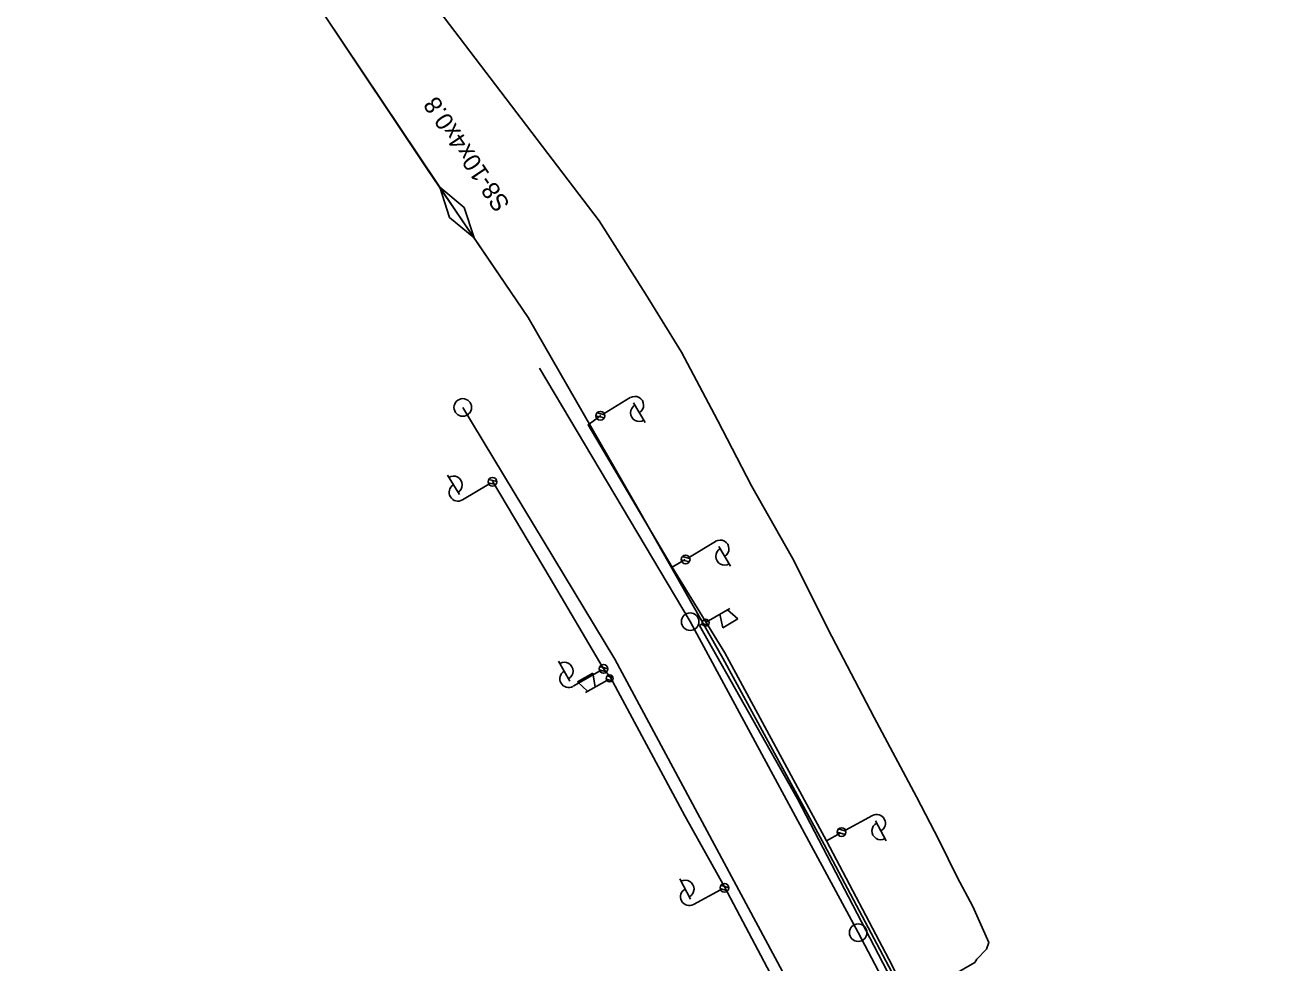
# Model space of a CAD drawing. Extents: x -748507 to -687366, y -1057342 to -1024924.
# Drawn here: x -745968.5 to -745824.4, y -1027172.3 to -1027065.4 of the extents above; entities that cross this region are included whole.
import ezdxf

# ---------------------------------------------------------------- set-up
doc = ezdxf.new("R2010")
doc.units = 0
for name, color, linetype in [('DK + TKK - SŽDC', 7, 'Continuous'), ('kanalizace ČD', 7, 'Continuous'), ('Sděl MK - SŽDC', 7, 'Continuous'), ('TK+DOK_Pha Holešovice - Kralupy', 7, 'Continuous'), ('Vedení NN - SŽDC', 7, 'Continuous'), ('ČEZ Distribuce - NN', 7, 'Continuous')]:
    doc.layers.add(name, color=color, linetype=linetype)

msp = doc.modelspace()

# ---------------------------------------------------------------- linework, layer by layer
at = {"layer": 'DK + TKK - SŽDC'}
msp.add_lwpolyline([(-745853.98, -1027207.17), (-745858.09, -1027198.24), (-745865.58, -1027181.9), (-745866.6, -1027178.75), (-745867.49, -1027177.72), (-745877.49, -1027158.8), (-745889.04, -1027137.58), (-745898.56, -1027120.82), (-745911.21, -1027098.73), (-745922.68, -1027081.89), (-745934.42, -1027064.27), (-745946.08, -1027047.16), (-745963.34, -1027024.99), (-745977.95, -1027005.62), (-745988.16, -1026993.76), (-745996.58, -1026983.71), (-746011.66, -1026965.97), (-746032.06, -1026944.1), (-746050.01, -1026925.99), (-746066.16, -1026911.08), (-746072.86, -1026906.1), (-746074.37, -1026904.96), (-746079.59, -1026900.36)], dxfattribs=at)
at = {"layer": 'kanalizace ČD'}
for points in [[(-745909.92, -1027104.51), (-745892.77, -1027133.4), (-745873.63, -1027168.84), (-745867.9, -1027179.71), (-745853.42, -1027211.13), (-745846.1, -1027228.53), (-745832.32, -1027263.34)], [(-745918.68, -1027108.99), (-745901.37, -1027137.67), (-745882.24, -1027173.28), (-745876.74, -1027184.07), (-745864.27, -1027210.97)]]:
    msp.add_lwpolyline(points, dxfattribs=at)
for centre in [(-745918.68, -1027108.99), (-745892.77, -1027133.4), (-745873.63, -1027168.84)]:
    msp.add_circle(centre, 1, dxfattribs=at)
at = {"layer": 'Sděl MK - SŽDC'}
for p, q in [((-745888.26, -1027131.89), (-745890.68, -1027133.3)), ((-745888.52, -1027132.04), (-745887.33, -1027133.09)), ((-745891.3, -1027133.24), (-745890.63, -1027133.42)), ((-745889.06, -1027134.09), (-745889.38, -1027132.54)), ((-745887.33, -1027133.09), (-745889.06, -1027134.09)), ((-745891.39, -1027133.63), (-745890.73, -1027133.81)), ((-745905.62, -1027140.27), (-745903.88, -1027139.28)), ((-745903.88, -1027139.28), (-745903.58, -1027140.83)), ((-745904.45, -1027141.32), (-745905.62, -1027140.27)), ((-745904.71, -1027141.47), (-745902.28, -1027140.09)), ((-745901.66, -1027140.15), (-745902.33, -1027139.96)), ((-745901.56, -1027139.76), (-745902.21, -1027139.58))]:
    msp.add_line(p, q, dxfattribs=at)
for points in [[(-745891.36, -1027133.66), (-745891.69, -1027133.85), (-745880.55, -1027153.59), (-745869.36, -1027175.07)], [(-745824.35, -1027282.11), (-745829.94, -1027262.87), (-745834.21, -1027258.02), (-745835.24, -1027253.5), (-745834.7, -1027253.35), (-745835.12, -1027252.54), (-745835.8, -1027252.55), (-745837.71, -1027253.38), (-745846.01, -1027257.16), (-745860.5, -1027222.63), (-745865.42, -1027211.36), (-745872.78, -1027195.68), (-745879.86, -1027180.63), (-745888.87, -1027163.61), (-745893.37, -1027155.53), (-745901.84, -1027139.78)]]:
    msp.add_lwpolyline(points, dxfattribs=at)
for centre in [(-745891.01, -1027133.52), (-745891.01, -1027133.52), (-745901.94, -1027139.87), (-745901.94, -1027139.87)]:
    msp.add_circle(centre, 0.401, dxfattribs=at)
at = {"layer": 'TK+DOK_Pha Holešovice - Kralupy'}
for points in [[(-745919.35, -1027086.77), (-745934.42, -1027064.27), (-745946.08, -1027047.16), (-745963.34, -1027024.99), (-745977.95, -1027005.62), (-745988.16, -1026993.76), (-745996.58, -1026983.71), (-746011.66, -1026965.97), (-746032.06, -1026944.1), (-746050.01, -1026925.99), (-746066.16, -1026911.08), (-746072.86, -1026906.1), (-746074.37, -1026904.96), (-746079.59, -1026900.36), (-746081.38, -1026898.4), (-746086.9, -1026891.58), (-746097.02, -1026882.38), (-746098.94, -1026881.12), (-746103.22, -1026877.45), (-746119.41, -1026862.13)], [(-745858.09, -1027198.24), (-745865.58, -1027181.9), (-745866.6, -1027178.75), (-745867.49, -1027177.72), (-745877.49, -1027158.8), (-745889.04, -1027137.58), (-745898.56, -1027120.82), (-745911.21, -1027098.73), (-745919.35, -1027086.77), (-745934.42, -1027064.27), (-745946.08, -1027047.16), (-745963.34, -1027024.99), (-745977.95, -1027005.62), (-745988.16, -1026993.76), (-745996.58, -1026983.71), (-746011.66, -1026965.97), (-746032.06, -1026944.1), (-746050.01, -1026925.99), (-746066.16, -1026911.08), (-746072.86, -1026906.1)], [(-745917.39, -1027089.67), (-745920.18, -1027087.33), (-745921.31, -1027083.87), (-745918.52, -1027086.21), (-745917.39, -1027089.67)], [(-745832.76, -1027256.58), (-745840.7, -1027236.81), (-745840.87, -1027236.57), (-745851.53, -1027213.24), (-745853.98, -1027207.17), (-745858.09, -1027198.24), (-745865.58, -1027181.9), (-745866.6, -1027178.75), (-745867.49, -1027177.72), (-745877.49, -1027158.8), (-745889.04, -1027137.58), (-745898.56, -1027120.82), (-745911.21, -1027098.73), (-745919.35, -1027086.77)]]:
    msp.add_lwpolyline(points, dxfattribs=at)
at = {"layer": 'Vedení NN - SŽDC'}
for p, q in [((-745902.58, -1027109.68), (-745899.59, -1027107.87)), ((-745899.22, -1027108.47), (-745897.88, -1027110.7)), ((-745903.51, -1027109.96), (-745902.58, -1027110.19)), ((-745903.38, -1027109.6), (-745902.53, -1027109.82)), ((-745919.07, -1027118.93), (-745920.42, -1027116.7)), ((-745914.92, -1027117.79), (-745915.77, -1027117.58)), ((-745914.79, -1027117.44), (-745915.72, -1027117.21)), ((-745915.72, -1027117.72), (-745918.71, -1027119.53)), ((-745892.86, -1027126.06), (-745889.87, -1027124.25)), ((-745889.51, -1027124.84), (-745888.16, -1027127.07)), ((-745893.67, -1027125.98), (-745892.81, -1027126.19)), ((-745893.79, -1027126.34), (-745892.86, -1027126.57)), ((-745906.47, -1027140.17), (-745907.77, -1027137.91)), ((-745903.09, -1027139.03), (-745906.12, -1027140.77)), ((-745902.29, -1027139.13), (-745903.14, -1027138.9)), ((-745902.16, -1027138.77), (-745903.08, -1027138.52)), ((-745875.08, -1027157.15), (-745872, -1027155.49)), ((-745871.67, -1027156.1), (-745870.44, -1027158.39)), ((-745876.02, -1027157.38), (-745875.1, -1027157.66)), ((-745875.88, -1027157.03), (-745875.04, -1027157.28)), ((-745892.72, -1027165.01), (-745893.95, -1027162.72)), ((-745888.37, -1027163.73), (-745889.29, -1027163.45)), ((-745889.31, -1027163.96), (-745892.39, -1027165.62)), ((-745888.51, -1027164.08), (-745889.35, -1027163.82))]:
    msp.add_line(p, q, dxfattribs=at)
for points in [[(-745894.82, -1027127.19), (-745904.4, -1027110.97), (-745902.96, -1027109.91)], [(-745915.31, -1027117.4), (-745908.73, -1027128.43), (-745902.68, -1027138.72), (-745901.84, -1027139.78), (-745893.37, -1027155.53), (-745888.87, -1027163.61), (-745879.86, -1027180.63), (-745872.78, -1027195.68), (-745865.42, -1027211.36), (-745861.09, -1027221.78), (-745860.5, -1027222.63), (-745857.08, -1027230.69), (-745851.54, -1027246.26), (-745847.36, -1027255.36), (-745845.82, -1027256.29), (-745846.01, -1027257.16), (-745837.71, -1027253.38), (-745833.99, -1027252.6), (-745834.49, -1027251.04), (-745835.49, -1027251.48), (-745839.2, -1027241.79), (-745837.59, -1027241.2)], [(-745877.25, -1027158.37), (-745888.83, -1027136.95), (-745894.82, -1027127.19), (-745893.35, -1027126.32)], [(-745861.47, -1027190.03), (-745861.73, -1027188.96), (-745869.76, -1027172.57), (-745877.25, -1027158.37), (-745875.59, -1027157.46)]]:
    msp.add_lwpolyline(points, dxfattribs=at)
for centre in [(-745903.01, -1027109.94), (-745903.01, -1027109.94), (-745915.29, -1027117.46), (-745915.29, -1027117.46), (-745893.29, -1027126.32), (-745893.29, -1027126.32), (-745902.65, -1027138.78), (-745902.65, -1027138.78), (-745875.52, -1027157.38), (-745875.52, -1027157.38), (-745888.87, -1027163.73), (-745888.87, -1027163.73)]:
    msp.add_circle(centre, 0.5, dxfattribs=at)
for centre, start, end in [((-745899.07, -1027108.73), 301.1156, 121.1156), ((-745898.56, -1027109.59), 120.413, 301.8181), ((-745919.74, -1027117.81), 300.4225, 121.8276), ((-745919.23, -1027118.67), 121.1251, 301.1251), ((-745889.35, -1027125.1), 301.1536, 121.1536), ((-745888.85, -1027125.96), 120.451, 301.8562), ((-745907.11, -1027139.03), 299.1292, 120.5344), ((-745906.62, -1027139.91), 119.8318, 299.8318), ((-745871.06, -1027157.25), 117.586, 298.9912), ((-745871.53, -1027156.37), 298.2886, 118.2886), ((-745893.33, -1027163.86), 297.6638, 119.069), ((-745892.86, -1027164.75), 118.3664, 298.3664)]:
    msp.add_arc(centre, 1, start, end, dxfattribs=at)
at = {"layer": 'ČEZ Distribuce - NN'}
for points in [[(-745860.33, -1027172.26), (-745860.12, -1027171.88), (-745858.99, -1027170.74), (-745858.74, -1027169.96), (-745860.58, -1027165.88), (-745862.36, -1027162.51), (-745864.4, -1027158.34), (-745866.98, -1027153.37), (-745871.82, -1027144.34), (-745876.62, -1027135.08), (-745881.1, -1027126.16), (-745885.8, -1027117.94), (-745889.66, -1027110.44), (-745893.75, -1027102.69), (-745897.85, -1027096.06), (-745903.15, -1027087.74), (-745982.69, -1026983.32), (-746018.18, -1026946.71), (-746061.43, -1026901.22), (-746117.93, -1026851.59)], [(-745907.03, -1027199.13), (-745860.33, -1027172.26)]]:
    msp.add_lwpolyline(points, dxfattribs=at)

# ---------------------------------------------------------------- texts
at = {"layer": 'TK+DOK_Pha Holešovice - Kralupy'}
msp.add_text('S8-10x4x0.8', height=2, rotation=124.0353, dxfattribs=at).set_placement((-745913.23, -1027085.82))

doc.saveas('drawing.dxf')
